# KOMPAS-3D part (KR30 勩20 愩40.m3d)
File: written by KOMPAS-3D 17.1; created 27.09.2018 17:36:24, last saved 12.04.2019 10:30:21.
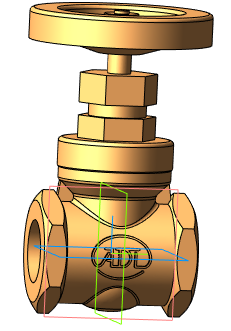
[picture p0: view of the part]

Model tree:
1. Операция без истории:2  (labels: Сталь 20  ГОСТ 1050-2013)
